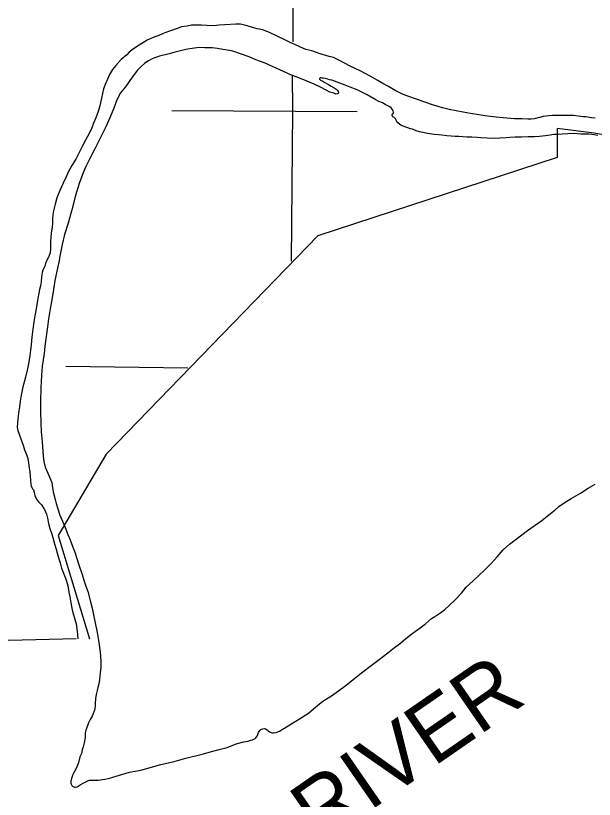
# Model space of a CAD drawing. Extents: x 1366406 to 1373462, y 376856 to 381998.
# Drawn here: x 1368458.3 to 1368554.2, y 380490.9 to 380620.7 of the extents above; entities that cross this region are included whole.
import ezdxf

# ---------------------------------------------------------------- set-up
doc = ezdxf.new("R2010")
doc.units = 0
for name, color, linetype in [('3', 7, 'Continuous'), ('4', 7, 'Continuous'), ('5', 7, 'Continuous'), ('9', 7, 'Continuous')]:
    doc.layers.add(name, color=color, linetype=linetype)

msp = doc.modelspace()

# ---------------------------------------------------------------- linework, layer by layer
at = {"layer": '3'}
msp.add_lwpolyline([(1368556.84, 380600.77), (1368554.15, 380601.22), (1368548.02, 380602.02), (1368548.03, 380597.22), (1368508.38, 380584.26), (1368473.3, 380548.06), (1368465.36, 380534.57), (1368470.55, 380517.45)], dxfattribs=at)
at = {"layer": '4'}
msp.add_lwpolyline([(1368288.63, 380522.18), (1368328.76, 380520.25), (1368371.38, 380518.1), (1368414.38, 380517.31), (1368457.17, 380517.23), (1368468.32, 380517.5)], dxfattribs=at)
at = {"layer": '5'}
for points in [[(1368503.5, 380777.34), (1368504.14, 380733.82), (1368503.81, 380690.86), (1368504.32, 380647.77), (1368504.22, 380616.37)], [(1368504.15, 380610.9), (1368504.19, 380604.98), (1368503.98, 380580.03)], [(1368484.17, 380605.01), (1368514.89, 380604.81)], [(1368466.62, 380562.64), (1368486.84, 380562.35)]]:
    msp.add_lwpolyline(points, dxfattribs=at)
at = {"layer": '9'}
for points in [[(1368554.34, 380603.74), (1368553.7, 380603.78), (1368552.75, 380603.93), (1368552.35, 380603.97), (1368550.75, 380604.17), (1368550.33, 380604.18), (1368549.79, 380604.17), (1368549.08, 380604.17), (1368547.69, 380604.17), (1368547.22, 380604.18), (1368546.66, 380604.12), (1368545.65, 380604.02), (1368545.15, 380603.86), (1368544.84, 380603.79), (1368544.25, 380603.64), (1368543.74, 380603.57), (1368543.15, 380603.56), (1368542.18, 380603.62), (1368540.96, 380603.63), (1368539.1, 380603.76), (1368537.92, 380603.89), (1368536.94, 380604), (1368536.08, 380604.1), (1368535.05, 380604.27), (1368533.68, 380604.49), (1368532.46, 380604.72), (1368531.27, 380604.94), (1368530.14, 380605.19), (1368529.03, 380605.47), (1368528.31, 380605.68), (1368527.36, 380605.94), (1368526.09, 380606.38), (1368524.7, 380606.88), (1368522.93, 380607.5), (1368522.31, 380607.79), (1368521.2, 380608.33), (1368520.07, 380608.99), (1368519.16, 380609.5), (1368518.34, 380609.95), (1368517.06, 380610.68), (1368515.37, 380611.56), (1368513.75, 380612.36), (1368511.96, 380613.3), (1368510.95, 380613.78), (1368510.26, 380613.97), (1368508.78, 380614.41), (1368507.4, 380614.86), (1368506.4, 380615.13), (1368505.51, 380615.49), (1368504.59, 380615.91), (1368503.78, 380616.29), (1368502.91, 380616.69), (1368501.65, 380617.31), (1368500.5, 380617.85), (1368499.28, 380618.36), (1368498.33, 380618.56), (1368497.57, 380618.77), (1368496.67, 380619.02), (1368495.56, 380619.32), (1368494.77, 380619.29), (1368492.99, 380619.18), (1368492.05, 380619.13), (1368491.13, 380619.05), (1368490.01, 380619.11), (1368489.12, 380619.13), (1368488.14, 380619.15), (1368487.43, 380619.15), (1368486.73, 380619), (1368485.8, 380618.84), (1368485.06, 380618.61), (1368483.98, 380618.21), (1368483.02, 380617.88)], [(1368483.02, 380617.88), (1368482.06, 380617.42), (1368481.53, 380617.24), (1368481.11, 380617.09), (1368480.12, 380616.64), (1368478.76, 380615.84), (1368477.85, 380615.2), (1368477.15, 380614.67), (1368476.72, 380614.25), (1368475.81, 380613.46), (1368474.94, 380612.45), (1368474.39, 380611.78), (1368473.84, 380610.95), (1368473.41, 380609.9), (1368473.26, 380609.56), (1368472.87, 380608.58), (1368472.54, 380607.06), (1368472.27, 380605.78), (1368472, 380604.85), (1368471.59, 380603.8), (1368471.24, 380602.9), (1368470.92, 380602.11), (1368470.57, 380601.32), (1368469.91, 380600.1), (1368469.35, 380599.05), (1368468.8, 380597.93), (1368468.31, 380596.94), (1368467.62, 380595.87), (1368467.1, 380594.87), (1368466.68, 380593.99), (1368466.17, 380592.94), (1368465.65, 380591.75), (1368465.17, 380590.53), (1368464.84, 380589.51), (1368464.61, 380588.39), (1368464.49, 380587.7), (1368464.45, 380587.05), (1368464.45, 380586.33), (1368464.37, 380585.7), (1368464.21, 380584.75), (1368464.16, 380583.89), (1368464.1, 380583.45), (1368464.12, 380582.85), (1368464.12, 380582.13), (1368464.04, 380581.43), (1368463.82, 380580.82), (1368463.72, 380580.58), (1368463.43, 380580.07), (1368463.28, 380579.68), (1368463.14, 380579.23), (1368462.83, 380578.55), (1368462.71, 380578.18), (1368462.64, 380577.71), (1368462.6, 380577.42), (1368462.57, 380576.62), (1368462.46, 380575.97), (1368462.28, 380575.33), (1368462.14, 380574.76), (1368461.99, 380573.84), (1368461.83, 380572.88), (1368461.71, 380572.16), (1368461.51, 380570.96), (1368461.33, 380569.97), (1368461.16, 380568.79), (1368461.02, 380567.46), (1368460.88, 380566.26), (1368460.76, 380565.3), (1368460.66, 380564.39), (1368460.46, 380563.05), (1368460.24, 380562), (1368459.97, 380560.83), (1368459.75, 380560.01), (1368459.52, 380559.23), (1368459.32, 380558.39), (1368459.22, 380557.83), (1368459.05, 380556.84), (1368458.95, 380555.93), (1368458.87, 380555.27), (1368458.76, 380554.37), (1368458.65, 380553.27), (1368458.6, 380552.48), (1368458.66, 380551.99), (1368458.89, 380551.37), (1368459.22, 380550.46), (1368459.56, 380549.55), (1368459.79, 380548.8), (1368460.11, 380548.01), (1368460.32, 380547.34), (1368460.45, 380546.64), (1368460.58, 380545.8), (1368460.68, 380545.06), (1368460.73, 380544.36), (1368460.78, 380543.82), (1368460.85, 380543.05), (1368460.89, 380542.84), (1368460.98, 380542.53), (1368461.09, 380542.32), (1368461.27, 380542.13), (1368461.39, 380541.76), (1368461.46, 380541.41), (1368461.51, 380541.24)], [(1368523.74, 380601.99), (1368523.29, 380602.11), (1368522.79, 380602.32), (1368522.77, 380602.32), (1368522.15, 380602.56), (1368521.91, 380602.71), (1368521.64, 380602.94), (1368521.47, 380603.17), (1368521.36, 380603.4), (1368521.26, 380603.6), (1368521.15, 380603.72), (1368520.99, 380603.87), (1368520.82, 380603.95), (1368520.72, 380604.05), (1368520.69, 380604.15), (1368520.68, 380604.18), (1368520.66, 380604.31), (1368520.7, 380604.41), (1368520.9, 380604.58), (1368520.92, 380604.73), (1368520.86, 380604.94), (1368520.81, 380605.07), (1368520.7, 380605.24), (1368520.54, 380605.44), (1368520.32, 380605.59), (1368520.1, 380605.72), (1368519.52, 380606.01), (1368519.06, 380606.26), (1368518.46, 380606.5), (1368517.87, 380606.81), (1368516.55, 380607.57), (1368514.87, 380608.42), (1368513.74, 380608.88), (1368512.88, 380609.2), (1368511.58, 380609.67), (1368510.69, 380610), (1368510.32, 380610.09), (1368510.04, 380610.19), (1368509.81, 380610.24), (1368509.59, 380610.28), (1368509.25, 380610.34), (1368509.09, 380610.37), (1368508.94, 380610.41), (1368508.84, 380610.41), (1368508.75, 380610.4), (1368508.68, 380610.35), (1368508.65, 380610.27), (1368508.63, 380610.17), (1368508.79, 380610.04), (1368509.08, 380609.89), (1368509.56, 380609.63), (1368510.13, 380609.33), (1368510.61, 380609.06), (1368511.07, 380608.76), (1368511.44, 380608.52), (1368511.63, 380608.3), (1368511.76, 380608.14), (1368511.8, 380607.94), (1368511.77, 380607.85), (1368511.73, 380607.8), (1368511.65, 380607.77), (1368511.37, 380607.69), (1368511.04, 380607.85), (1368510.38, 380608.05), (1368509.74, 380608.36), (1368508.8, 380608.87), (1368507.79, 380609.39), (1368506.42, 380609.89), (1368504.95, 380610.51), (1368504.04, 380610.85), (1368502.71, 380611.47), (1368500.96, 380612.23), (1368499.63, 380612.83), (1368498.11, 380613.41), (1368497, 380613.89), (1368495.57, 380614.38), (1368494.29, 380614.84), (1368493.74, 380614.94), (1368492.65, 380615.12), (1368491.78, 380615.29), (1368490.9, 380615.37), (1368489.66, 380615.41), (1368488.71, 380615.42), (1368487.17, 380615.24), (1368486.52, 380615.09), (1368484.54, 380614.63), (1368483.75, 380614.4), (1368482.16, 380613.98), (1368481.07, 380613.61), (1368480.22, 380613.16), (1368479.66, 380612.79), (1368479.14, 380612.35), (1368478.51, 380611.7), (1368477.63, 380610.53), (1368476.49, 380608.9), (1368475.71, 380607.92), (1368475.06, 380606.75), (1368474.56, 380605.39), (1368473.93, 380603.77), (1368473.24, 380602.32), (1368472.31, 380600.44)], [(1368554.77, 380600.88), (1368554.14, 380600.96), (1368553.74, 380601.04), (1368553.27, 380601.08), (1368552.87, 380601.07), (1368552.59, 380601.08), (1368552.58, 380601.08), (1368551.95, 380601.07), (1368551.33, 380601.15), (1368550.8, 380601.18), (1368549.76, 380601.13), (1368548.87, 380601.09), (1368548.21, 380601.04), (1368547.43, 380601), (1368546.88, 380600.94), (1368546.09, 380600.82), (1368545.07, 380600.68), (1368544.24, 380600.65), (1368543.21, 380600.62), (1368542.09, 380600.6), (1368541.05, 380600.57), (1368540.16, 380600.52), (1368539.56, 380600.47), (1368538.53, 380600.4), (1368537.56, 380600.38), (1368536.4, 380600.42), (1368535.38, 380600.45), (1368534.75, 380600.52), (1368533.89, 380600.57), (1368533.13, 380600.59), (1368532.41, 380600.64), (1368531.73, 380600.68), (1368531.1, 380600.71), (1368530.48, 380600.74), (1368529.76, 380600.79), (1368528.9, 380600.89), (1368528.34, 380600.95), (1368527.64, 380601), (1368526.55, 380601.17), (1368525.78, 380601.33), (1368525.21, 380601.45), (1368524.64, 380601.66), (1368524.04, 380601.89), (1368523.74, 380601.99)], [(1368472.31, 380600.44), (1368471.45, 380598.65), (1368470.55, 380596.93), (1368469.95, 380595.72), (1368469.49, 380594.66), (1368468.89, 380593.05), (1368468.26, 380590.92), (1368467.62, 380588.54), (1368467, 380586.33), (1368466.41, 380584.46), (1368466.02, 380582.79), (1368465.67, 380581.12), (1368465.45, 380579.88), (1368465.12, 380578.37), (1368464.82, 380576.84), (1368464.59, 380575.34), (1368464.37, 380573.98), (1368464.02, 380572.16), (1368463.78, 380570.47), (1368463.59, 380569.17), (1368463.38, 380567.57), (1368463.18, 380565.95), (1368463.03, 380564.72), (1368462.74, 380562.66), (1368462.58, 380561.07), (1368462.48, 380559.09), (1368462.46, 380556.78), (1368462.44, 380555.17), (1368462.48, 380553.22), (1368462.55, 380551.76), (1368462.71, 380550.12), (1368462.84, 380548.49), (1368462.86, 380547.8), (1368463, 380546.84), (1368463.1, 380546.35), (1368463.28, 380545.78), (1368463.84, 380544.55), (1368464.3, 380543.37), (1368464.41, 380542.56), (1368464.54, 380541.81), (1368464.89, 380540.55), (1368465.05, 380539.89), (1368465.31, 380538.98), (1368465.64, 380537.95), (1368466.09, 380536.96), (1368466.52, 380535.91), (1368466.98, 380534.77), (1368467.33, 380533.85), (1368467.81, 380532.65), (1368468.12, 380531.85), (1368468.75, 380529.87), (1368469.33, 380528.1), (1368469.64, 380527.19), (1368469.91, 380526.38), (1368470.28, 380525.29), (1368470.73, 380523.62), (1368470.98, 380522.53), (1368471.29, 380521.19), (1368471.48, 380520.14), (1368471.83, 380518.54), (1368472.12, 380516.86), (1368472.3, 380515.24), (1368472.41, 380513.77), (1368472.41, 380512.78), (1368472.31, 380511.81), (1368472.22, 380510.72), (1368472.09, 380509.99), (1368471.95, 380509.43), (1368471.83, 380508.89), (1368471.67, 380508.23), (1368471.55, 380507.5), (1368471.52, 380506.75), (1368471.51, 380506.27), (1368471.4, 380505.63), (1368470.99, 380504.65), (1368470.64, 380504.11), (1368470.37, 380503.53), (1368470.08, 380502.61), (1368469.96, 380502.35), (1368469.85, 380501.82), (1368469.81, 380501.12), (1368469.66, 380500.24), (1368469.48, 380499.56), (1368469.36, 380499.06), (1368469.22, 380498.45), (1368468.98, 380497.93), (1368468.79, 380497.21), (1368468.72, 380496.93), (1368468.65, 380496.79), (1368468.43, 380496.27), (1368468.27, 380495.88), (1368467.84, 380495.1), (1368467.73, 380494.86), (1368467.72, 380494.82), (1368467.58, 380494.34), (1368467.49, 380494.1), (1368467.46, 380493.92), (1368467.45, 380493.71), (1368467.48, 380493.53), (1368467.53, 380493.37), (1368467.57, 380493.27)], [(1368467.57, 380493.27), (1368467.63, 380493.17), (1368467.75, 380493.05), (1368467.94, 380492.95), (1368468.07, 380492.9), (1368468.23, 380492.91), (1368468.49, 380492.97), (1368468.67, 380493.08), (1368469.01, 380493.3), (1368469.6, 380493.6), (1368470.07, 380493.85), (1368470.24, 380493.94), (1368470.56, 380494.03), (1368471.19, 380494.05), (1368471.97, 380494.05), (1368473.09, 380494.19), (1368473.72, 380494.34), (1368474.42, 380494.57), (1368477.2, 380495.37), (1368479.04, 380495.71), (1368482.35, 380496.63), (1368484.6, 380497.15), (1368486.52, 380497.7), (1368489.41, 380498.42), (1368490.79, 380498.78), (1368492.06, 380499.11), (1368493.33, 380499.45), (1368494.86, 380500.07), (1368496.13, 380500.4), (1368496.78, 380500.5), (1368497.28, 380500.66), (1368497.56, 380500.76), (1368497.77, 380500.87), (1368497.98, 380500.97), (1368498.13, 380501.08), (1368498.33, 380501.33), (1368498.43, 380501.64), (1368498.54, 380501.96), (1368498.77, 380502.3), (1368498.93, 380502.42), (1368499.26, 380502.55), (1368499.53, 380502.59), (1368499.73, 380502.55), (1368500, 380502.39), (1368500.16, 380502.25), (1368500.38, 380502.05), (1368500.54, 380501.98), (1368500.73, 380501.9), (1368501.01, 380501.88), (1368501.49, 380501.96), (1368502.05, 380502.16), (1368503.88, 380503.33), (1368505.34, 380504.21), (1368506.82, 380505.17), (1368508.05, 380506.21), (1368509.22, 380507.16), (1368510.81, 380508.16), (1368511.66, 380508.75), (1368512.61, 380509.47), (1368513.37, 380510.02), (1368514.53, 380510.94), (1368515.6, 380511.84), (1368517.23, 380513.04), (1368518.51, 380514.02), (1368519.97, 380515.13), (1368521.07, 380516.02), (1368522.06, 380516.76), (1368522.93, 380517.5), (1368523.95, 380518.28), (1368524.57, 380518.75), (1368525.33, 380519.29), (1368526.23, 380519.97), (1368527.22, 380520.81), (1368527.76, 380521.14), (1368528.75, 380521.84), (1368529.37, 380522.26), (1368531.05, 380523.85), (1368532.19, 380525.06), (1368532.94, 380526.05), (1368534.12, 380527.09), (1368535.1, 380527.99), (1368535.92, 380528.79), (1368537.11, 380529.96), (1368538.1, 380531.08), (1368539.1, 380532.23), (1368540.12, 380533.17), (1368540.76, 380533.67), (1368543.09, 380535.4), (1368545.47, 380537.07), (1368546.92, 380538.24), (1368547.61, 380538.76), (1368548.27, 380539.38), (1368549.19, 380540), (1368550.35, 380540.7), (1368551.9, 380541.61), (1368553.18, 380542.42), (1368554.3, 380543.09)], [(1368461.51, 380541.24), (1368461.8, 380540.6), (1368462.08, 380540.17), (1368462.59, 380539.65), (1368463.09, 380538.88), (1368463.41, 380538.14), (1368463.59, 380537.44), (1368463.77, 380536.59), (1368464.01, 380535.76), (1368464.25, 380534.97), (1368464.47, 380534.28), (1368464.78, 380533.22), (1368465.01, 380532.34), (1368465.23, 380531.47), (1368465.47, 380530.72), (1368465.7, 380530.05), (1368465.94, 380529.2), (1368466.22, 380528.36), (1368466.4, 380527.92), (1368466.57, 380527.53), (1368466.74, 380527.02), (1368466.95, 380526.25), (1368467.04, 380525.86), (1368467.18, 380524.9), (1368467.27, 380524.43), (1368467.47, 380523.41), (1368467.71, 380522.29), (1368467.92, 380521.44), (1368468.08, 380520.88), (1368468.34, 380519.98), (1368468.48, 380519.15), (1368468.59, 380518.21), (1368468.63, 380517.49)]]:
    msp.add_lwpolyline(points, dxfattribs=at)

# ---------------------------------------------------------------- texts
msp.add_text('RIVER', height=10.264, rotation=34.6578, dxfattribs=at).set_placement((1368508.7, 380483.16))

doc.saveas('drawing.dxf')
